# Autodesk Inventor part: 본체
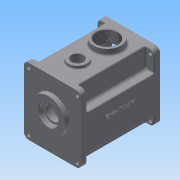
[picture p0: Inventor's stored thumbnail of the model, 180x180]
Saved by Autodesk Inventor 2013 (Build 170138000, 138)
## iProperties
Created: 2016-02
Part Number: 본체
Material: 알루미늄 6061
Document SubType Name: Modeling
Designer: mduedu
Density: 1 g/cm^3
Author: mduedu
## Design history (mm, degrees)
sketch "스케치1"
  geometry: L1 (-47, -47)-(47, -47); L2 (47, -47)-(47, 63); L3 (47, 63)-(-47, 63); L4 (-47, 63)-(-47, -47); 2 further points
  constraints: 8 end point, 2 parallel, 1 horizontal, 1 midpoint, 1 perpendicular, 1 vertical alignment
  dimensions: "d0" = 94 distance of L2.end L3.end; "d155" = 110 distance of L1.end L2.end; "d156" = 47 distance from line of L1 point (0, 0)
extrude "돌출1" new body sketch "스케치1" distance "d2" = 130; taper "d3" = 0 deg
sketch "스케치3"
  geometry: C1 r 40 at (0, 0); 1 further point
  constraints: 1 centre point, 1 coincident
  dimensions: "d9" = 80 diameter of C1
extrude "돌출3" cut sketch "스케치3" distance "d11" = 121; taper "d12" = 0 deg
sketch "스케치4"
  geometry: C1 r 21 at (0, 11); 1 further point
  constraints: 1 centre point, 1 vertical alignment
  dimensions: "d13" = 21 radius of C1; "d15" = 11 distance of point (0, 0) C1.centre
extrude "돌출4" join sketch "스케치4" distance "d16" = 7; taper "d17" = 0 deg
sketch "스케치5"
  geometry: C1 r 15 at (0, -20); 1 further point
  constraints: 1 centre point, 1 vertical alignment
  dimensions: "d18" = 15 radius of C1; "d20" = 20 distance of point (0, 0) C1.centre
extrude "돌출5" join sketch "스케치5" distance "d21" = 7; taper "d22" = 0 deg
sketch "스케치6"
  geometry: C1 r 28 at (0, 11); A1 r 21 centre (0, 11) between (8.978, -7.984) and (-8.978, -7.984) reference; 1 further point
  constraints: 1 centre point, 1 coincident
  dimensions: "d23" = 56 diameter of C1
extrude "돌출6" join sketch "스케치6" distance "d25" = 7; taper "d26" = -3 deg
hole "구멍1" diameter "d29" = 35; stored, may be unused: countersink angle "d33" = 90 deg, drill point angle "d35" = 0 deg; dims "d27" = 10, "d28" = 10, "d30" = 6, "d31" = 4, "d32" = 2, "d34" = 10
hole "구멍2" diameter "d38" = 22; stored, may be unused: countersink angle "d42" = 90 deg, drill point angle "d44" = 0 deg; dims "d36" = 10, "d37" = 10, "d39" = 6, "d40" = 4, "d41" = 2, "d43" = 7
hole "구멍3" diameter "d47" = 19; stored, may be unused: countersink angle "d51" = 90 deg, drill point angle "d53" = 0 deg; dims "d45" = 10, "d46" = 10, "d48" = 6, "d49" = 4, "d50" = 2, "d52" = 1
hole "구멍4" diameter "d56" = 32; stored, may be unused: countersink angle "d60" = 90 deg, drill point angle "d62" = 0 deg; dims "d54" = 10, "d55" = 10, "d57" = 6, "d58" = 4, "d59" = 2, "d61" = 8
hole "구멍5" diameter "d65" = 25; stored, may be unused: countersink angle "d69" = 90 deg, drill point angle "d71" = 0 deg; dims "d63" = 10, "d64" = 10, "d66" = 6, "d67" = 4, "d68" = 2, "d70" = 8
fillet "모깎기2" dims "d73" = 0.3
fillet "모깎기3" dims "d74" = 2
chamfer "모따기1" distance "d75" = 1; stored, may be unused: second distance "d76" = 2, angle "d77" = 45 deg
fillet "모깎기4" dims "d78" = 3
sketch "스케치16"
  geometry: L1 (-23, 32.726)-(23, 32.726); L2 (23, 32.726)-(23, 53); L3 (23, 53)-(-23, 53); L4 (-23, 53)-(-23, 32.726); L5 (-47, 63)-(47, 63) reference; 3 further points
  constraints: 8 end point, 2 parallel, 1 horizontal, 1 midpoint, 1 perpendicular, 1 vertical alignment, 2 other
  dimensions: "d160" = 46 distance of L2.end L3.end; "d163" = 10 distance between parallel lines of L3 L5
extrude "돌출15" cut sketch "스케치16" stored distance "d164" = 10; taper "d165" = 0 deg
fillet "모깎기5" dims "d79" = 2
fillet "모깎기15" dims "d166" = 5
sketch "스케치7"
  geometry: L1 (-23, 48)-(-23, 35.228) reference; L2 (23, 35.228)-(23, 48) reference; L3 (18, 53)-(-18, 53) reference; L4 (47, 63)-(47, -47) reference; L5 (47, -47)-(-47, -47) reference; L6 (-47, -47)-(-47, 63) reference; L7 (-47, 63)-(47, 63) reference; L8 (-26, 48)-(-26, 35.228); L9 (26, 35.228)-(26, 48); L10 (18, 56)-(-18, 56); C1 r 43 at (0, 0); A1 r 5 centre (-18, 48) between (-18, 53) and (-23, 48) reference; A2 r 5 centre (-28, 35.228) between (-24.889, 31.314) and (-23, 35.228) reference; A3 r 40 centre (0, 0) between (-24.889, 31.314) and (24.889, 31.314) reference; A4 r 5 centre (28, 35.228) between (23, 35.228) and (24.889, 31.314) reference; A5 r 5 centre (18, 48) between (23, 48) and (18, 53) reference; A6 r 8 centre (-18, 48) between (-18, 56) and (-26, 48); A7 r 2 centre (-28, 35.228) between (-26.756, 33.662) and (-26, 35.228); A8 r 43 centre (0, 0) between (-26.756, 33.662) and (26.756, 33.662); A9 r 2 centre (28, 35.228) between (26, 35.228) and (26.756, 33.662); A10 r 8 centre (18, 48) between (26, 48) and (18, 56); 1 further point
  constraints: 10 point on circle, 6 centre point, 6 end point, 1 coincident, 7 other
  dimensions: "d80" = 86 diameter of C1; "d167" = 3 distance between parallel lines of L3 L10
extrude "돌출7" cut sketch "스케치7" distance "d83" = 9; taper "d84" = 0 deg
sketch "스케치8" dims "d168" = 36
  geometry: L1 (-36, 4)-(-39.799, 4); L2 (-36, -4)-(-39.799, -4); A1 r 4 centre (-36, 0) between (-36, 4) and (-36, -4); A2 r 40 centre (0, 0) between (-24.889, 31.314) and (24.889, 31.314) reference; A3 r 40 centre (0, 0) between (-39.799, 4) and (-39.799, -4); 2 further points
  constraints: 5 point on circle, 4 end point, 2 centre point, 2 coincident, 2 horizontal alignment, 2 tangent, 1 horizontal, 1 parallel, 2 other
  dimensions: "d169" = 4 radius of A1
extrude "돌출9" join sketch "스케치8" stored distance "d89" = 9; taper "d90" = 0 deg
fillet "모깎기6" dims "d91" = 3.5
node "작업 평면1"
sketch "스케치9"
  geometry: L1 (47, 63)-(33, 63); L2 (33, 63)-(33, 30); L3 (33, 30)-(47, 30); L4 (47, 30)-(47, 63); L5 (47, 63)-(-47, 63) reference; L6 (47, -47)-(47, 63) reference; A1 r 40 centre (0, 0) between (-39.148, -8.214) and (39.148, -8.214) reference; 1 further point
  constraints: 8 end point, 2 parallel, 1 coincident, 1 horizontal, 1 perpendicular
  dimensions: "d95" = 33 distance from line of L2 point (0, 0); "d96" = 30 distance from line of L3 point (0, 0)
extrude "돌출10" cut sketch "스케치9" distance "d97" = 110; taper "d98" = 0 deg
sketch "스케치11"
  geometry: L1 (-40, -40)-(40, -40); L2 (40, -40)-(40, 56); L3 (40, 56)-(-40, 56); L4 (-40, 56)-(-40, -40); L5 (-47, -47)-(47, -47) reference; L6 (47, 63)-(-47, 63) reference; L7 (-47, 63)-(-47, -47) reference; C1 r 3.5 at (-40, 56); C2 r 3.5 at (40, 56); C3 r 3.5 at (40, -40); C4 r 3.5 at (-40, -40); 1 further point
  constraints: 8 end point, 4 centre point, 4 coincident, 3 equal radius, 2 parallel, 1 horizontal, 1 perpendicular
  dimensions: "d109" = 80 distance of L2.end L3.end; "d112" = 7 diameter of C1; "d157" = 7 distance from line of L1.start L5; "d158" = 7 distance between parallel lines of L6 L3; "d159" = 7 distance from line of L7 L3.end
extrude "돌출12" cut sketch "스케치11" stored distance "d113" = 63; taper "d114" = 0 deg
fillet "모깎기7" dims "d115" = 8, "d187" = 8
fillet "모깎기8" dims "d116" = 5
fillet "모깎기11" dims "d119" = 2, "d188" = 2
fillet "모깎기12" dims "d120" = 2
fillet "모깎기13" dims "d121" = 2
sketch "스케치12"
  geometry: 3 further points
  constraints: 2 horizontal alignment
hole "구멍6" sketch "스케치12" at (36, 0), (-36, 0) diameter "d122" = 3.242; stored, may be unused: countersink angle "d126" = 90 deg, drill point angle "d128" = 120 deg; dims "d123" = 7, "d124" = 4, "d125" = 2, "d127" = 9
fillet "모깎기14" dims "d147" = 0.3
chamfer "모따기4" distance "d151" = 1; stored, may be unused: second distance "d152" = 2, angle "d153" = 45 deg
sketch "스케치20"
  geometry: L1 (74, -122)-(78, -122) reference; L2 (70, -12)-(70, -118) reference; L3 (78, -8)-(74, -8) reference; L4 (78, 0)-(78, -8) reference; L5 (78, 0)-(0, 0) reference; L6 (0, -8)-(0, 0) reference; L7 (4, -8)-(0, -8) reference; L8 (8, -118)-(8, -12) reference; L9 (0, -122)-(4, -122) reference; L10 (0, -130)-(0, -122) reference; L11 (78, -130)-(0, -130) reference; L12 (78, -122)-(78, -130) reference; L13 (39, 0)-(39, -130); C1 r 10 at (39, -89); A1 r 4 centre (74, -118) between (70, -118) and (74, -122) reference; A2 r 4 centre (74, -12) between (74, -8) and (70, -12) reference; A3 r 4 centre (4, -12) between (8, -12) and (4, -8) reference; A4 r 4 centre (4, -118) between (4, -122) and (8, -118) reference
  constraints: 2 end point, 1 centre point, 1 midpoint, 1 point on line
  dimensions: "d189" = 20 diameter of C1; "d190" = 41 distance from line of C1.centre L11
extrude "돌출19" cut sketch "스케치20" stored distance "d191" = 10; taper "d192" = 0 deg
sketch "스케치18"
  geometry: C1 r 15 at (39, -89); C2 r 10 at (39, -89) reference; 1 further point
  constraints: 1 centre point, 1 concentric
  dimensions: "d174" = 30 diameter of C1
extrude "돌출17" join sketch "스케치18" distance "d175" = 5; taper "d176" = 0 deg
fillet "모깎기16" dims "d177" = 2
sketch "스케치19"
  geometry: C1 r 10 at (18, 80) reference; C2 r 15 at (18, 80); 1 further point
  constraints: 1 centre point, 1 coincident
  dimensions: "d178" = 30 diameter of C2
extrude "돌출18" cut sketch "스케치19" distance "d181" = 5; taper "d182" = 0 deg
chamfer "모따기5" distance "d183" = 0.5; stored, may be unused: second distance "d184" = 2, angle "d185" = 45 deg
sketch "스케치21"
  geometry: L1 (-122, 7)-(-122, 0) reference; L2 (-12, 11)-(-118, 11) reference; L3 (-8, 0)-(-8, 7) reference; L4 (0, 0)-(-8, 0) reference; L5 (0, 0)-(0, 94) reference; L6 (-8, 94)-(0, 94) reference; L7 (-8, 71)-(-8, 94) reference; L8 (-118, 67)-(-12, 67) reference; L9 (-122, 94)-(-122, 71) reference; L10 (-130, 94)-(-122, 94) reference; L11 (-130, 0)-(-130, 94) reference; L12 (-122, 0)-(-130, 0) reference; L13 (-130, 47)-(0, 47); A1 r 4 centre (-118, 7) between (-118, 11) and (-122, 7) reference; A2 r 4 centre (-12, 7) between (-8, 7) and (-12, 11) reference; A3 r 4 centre (-12, 71) between (-12, 67) and (-8, 71) reference; A4 r 4 centre (-118, 71) between (-122, 71) and (-118, 67) reference; 3 further points
  constraints: 3 midpoint, 2 end point, 1 coincident, 1 other
feature "엠보싱2" sketch "스케치21" dims "d193" = 0.5, "d194" = 0
sketch "스케치22"
  geometry: L1 (74, -122)-(78, -122) reference; L2 (70, -12)-(70, -118) reference; L3 (78, -8)-(74, -8) reference; L4 (78, 0)-(78, -8) reference; L5 (78, 0)-(0, 0) reference; L6 (0, -8)-(0, 0) reference; L7 (4, -8)-(0, -8) reference; L8 (8, -118)-(8, -12) reference; L9 (0, -122)-(4, -122) reference; L10 (0, -130)-(0, -122) reference; L11 (78, -130)-(0, -130) reference; L12 (78, -122)-(78, -130) reference; L13 (39, -130)-(39, 0); C1 r 17 at (39, -89) reference; C2 r 22.5 at (39, -40); A1 r 4 centre (74, -118) between (70, -118) and (74, -122) reference; A2 r 4 centre (74, -12) between (74, -8) and (70, -12) reference; A3 r 4 centre (4, -12) between (8, -12) and (4, -8) reference; A4 r 4 centre (4, -118) between (4, -122) and (8, -118) reference
  constraints: 2 end point, 1 centre point, 1 midpoint, 1 parallel, 1 point on line
  dimensions: "d195" = 45 diameter of C2; "d197" = 40 distance from line of C2.centre L5
extrude "돌출20" join sketch "스케치22" distance "d198" = 10; taper "d199" = 0 deg
fillet "모깎기17" dims "d200" = 3
hole "구멍7" diameter "d203" = 35; stored, may be unused: countersink angle "d207" = 90 deg, drill point angle "d209" = 118 deg; dims "d204" = 6, "d205" = 4, "d206" = 2, "d208" = 8, "d213" = 10, "d214" = 10
feature "스레드1" dims "d215" = 10, "d216" = 0
chamfer "모따기6" distance "d210" = 1; stored, may be unused: second distance "d211" = 2, angle "d212" = 45 deg
node "솔리드1"
pattern_circular "원형 패턴1" dims angle "d93" = 360 deg
mirror "대칭1"
mirror "대칭2"
node "투영된 루프1"
node "투영된 루프2"
node "투영된 루프3"
node "절단 모서리 투영3"
